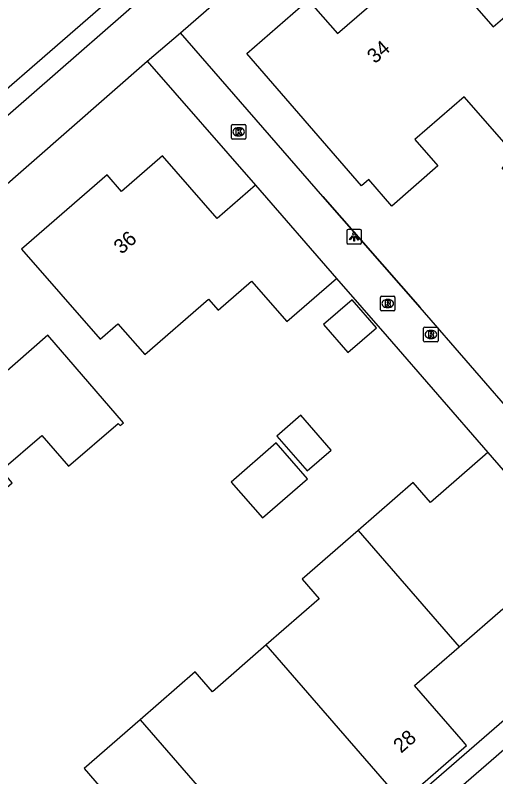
# Model space of a CAD drawing. Extents: x 155888 to 156864, y 383882 to 384671.
# Drawn here: x 156044.5 to 156077.4, y 384100.3 to 384152.6 of the extents above; entities that cross this region are included whole.
import ezdxf

# ---------------------------------------------------------------- set-up
doc = ezdxf.new("R2010")
doc.units = 0
for name, color, linetype in [('IMGEO_Kolk', 7, 'Continuous'), ('IMGEO_Lichtpunt', 7, 'Continuous'), ('IMGEO_Muur', 7, 'Continuous'), ('IMGEO_Pand', 7, 'Continuous'), ('IMGEO_Pand_nummerreeks', 7, 'Continuous'), ('IMGEO_Pand_overbouw', 7, 'Continuous'), ('IMGEO_Rijbaan_lokaal_gesloten', 7, 'Continuous'), ('IMGEO_Rioolput', 7, 'Continuous'), ('IMGEO_Voetpad_open', 7, 'Continuous')]:
    doc.layers.add(name, color=color, linetype=linetype)

msp = doc.modelspace()

# ---------------------------------------------------------------- linework, layer by layer
at = {"layer": 'IMGEO_Kolk'}
for p, q in [((156059.363, 384145.059), (156060.215, 384145.059)), ((156059.288, 384144.133), (156059.288, 384144.985)), ((156059.776, 384144.839), (156059.801, 384144.839)), ((156060.289, 384144.985), (156060.289, 384144.133)), ((156060.215, 384144.059), (156059.363, 384144.059)), ((156059.799, 384144.279), (156059.774, 384144.279))]:
    msp.add_line(p, q, dxfattribs=at)
for points in [[(156059.363, 384145.059), (156060.215, 384145.059)], [(156059.288, 384144.133), (156059.288, 384144.985)], [(156059.609, 384144.759), (156059.732, 384144.759), (156059.732, 384144.608), (156059.862, 384144.759), (156060.026, 384144.759), (156059.88, 384144.608), (156060.033, 384144.359), (156059.881, 384144.359), (156059.796, 384144.523), (156059.732, 384144.456), (156059.732, 384144.359), (156059.609, 384144.359), (156059.609, 384144.759)], [(156060.289, 384144.985), (156060.289, 384144.133)], [(156060.215, 384144.059), (156059.363, 384144.059)]]:
    msp.add_lwpolyline(points, dxfattribs=at)
for centre, start, end in [((156059.365, 384144.983), 91.552, 178.448), ((156059.365, 384144.983), 91.552, 178.448), ((156060.213, 384144.983), 1.552, 88.448), ((156060.213, 384144.983), 1.552, 88.448), ((156059.365, 384144.135), 181.552, 268.448), ((156059.365, 384144.135), 181.552, 268.448), ((156060.213, 384144.135), 271.552, 358.448), ((156060.213, 384144.135), 271.552, 358.448)]:
    msp.add_arc(centre, 0.0765, start, end, dxfattribs=at)
for centre, major_axis, ratio, start_param, end_param in [((156059.775, 384144.559), (-0.387, 0.002), 0.722429, 4.712389, 7.853982), ((156059.8, 384144.559), (-0.39, 0.002), 0.717154, 1.570796, 4.712389)]:
    msp.add_ellipse(centre, major_axis=major_axis, ratio=ratio, start_param=start_param, end_param=end_param, dxfattribs=at)
at = {"layer": 'IMGEO_Lichtpunt'}
for p, q in [((156067.218, 384137.759), (156067.218, 384136.952)), ((156067.218, 384137.759), (156067.218, 384136.952)), ((156068.12, 384137.854), (156067.312, 384137.854)), ((156068.12, 384137.854), (156067.312, 384137.854)), ((156068.214, 384136.952), (156068.214, 384137.759)), ((156068.214, 384136.952), (156068.214, 384137.759)), ((156067.312, 384136.858), (156068.12, 384136.858)), ((156067.312, 384136.858), (156068.12, 384136.858))]:
    msp.add_line(p, q, dxfattribs=at)
for points in [[(156067.592, 384137.423), (156067.631, 384137.395), (156067.443, 384137.133), (156067.405, 384137.16), (156067.592, 384137.423)], [(156067.694, 384137.375), (156067.741, 384137.375), (156067.741, 384137.053), (156067.694, 384137.053), (156067.694, 384137.375)], [(156067.804, 384137.395), (156067.842, 384137.422), (156068.029, 384137.16), (156067.99, 384137.132), (156067.804, 384137.395)]]:
    msp.add_lwpolyline(points, dxfattribs=at)
msp.add_circle((156067.717, 384137.557), 0.0994, dxfattribs=at)
for centre, start, end in [((156067.312, 384137.759), 90, 180), ((156067.312, 384137.759), 90, 180), ((156068.12, 384137.759), 0, 90), ((156068.12, 384137.759), 0, 90), ((156067.312, 384136.952), 180, 270), ((156067.312, 384136.952), 180, 270), ((156068.12, 384136.952), 270, 0), ((156068.12, 384136.952), 270, 360)]:
    msp.add_arc(centre, 0.0946, start, end, dxfattribs=at)
at = {"layer": 'IMGEO_Muur'}
for points in [[(156065.559, 384140.115), (156072.254, 384132.504)], [(156066.498, 384134.486), (156069.973, 384130.498)]]:
    msp.add_lwpolyline(points, dxfattribs=at)
at = {"layer": 'IMGEO_Pand'}
for points in [[(156080.234, 384139.361), (156077.863, 384142.085), (156078.799, 384142.9), (156075.259, 384146.968), (156071.885, 384144.032), (156073.462, 384142.221), (156070.292, 384139.462), (156068.71, 384141.281), (156068.227, 384140.861), (156060.347, 384149.929), (156064.566, 384153.595), (156066.561, 384151.3), (156070.043, 384154.326), (156072.878, 384156.789), (156077.25, 384151.765), (156078.043, 384152.455), (156083.1, 384146.644), (156085.471, 384143.92), (156081.936, 384140.842)], [(156060.939, 384140.901), (156058.302, 384138.603), (156054.555, 384142.902), (156051.76, 384140.467), (156050.764, 384141.61), (156044.892, 384136.493), (156050.276, 384130.315), (156051.502, 384131.383), (156053.349, 384129.264), (156057.718, 384133.071), (156058.375, 384132.317), (156060.665, 384134.313), (156063.089, 384131.532), (156066.498, 384134.486)], [(156060.939, 384140.901), (156066.498, 384134.486)], [(156067.285, 384129.413), (156069.236, 384131.104), (156067.567, 384133.029), (156065.616, 384131.339), (156067.285, 384129.413)], [(156040.149, 384116.917), (156044.251, 384120.459), (156043.505, 384121.324), (156046.28, 384123.72), (156048.113, 384121.597), (156051.525, 384124.544), (156051.656, 384124.392), (156051.884, 384124.589), (156046.703, 384130.589), (156043.311, 384127.654), (156039.612, 384131.91), (156037.93, 384130.448), (156037.204, 384131.284), (156034.303, 384128.763), (156035.041, 384127.914), (156033.379, 384126.47), (156037.473, 384121.726), (156036.639, 384120.981), (156040.149, 384116.917)], [(156064.496, 384121.274), (156066.14, 384122.702), (156064.054, 384125.103), (156062.41, 384123.675), (156064.496, 384121.274)], [(156064.509, 384120.736), (156062.367, 384123.202), (156059.274, 384120.515), (156061.416, 384118.049), (156064.509, 384120.736)], [(156076.889, 384122.539), (156072.948, 384119.116), (156071.768, 384120.475), (156067.993, 384117.196)], [(156076.889, 384122.539), (156086.213, 384111.78)], [(156067.993, 384117.196), (156064.143, 384113.853), (156065.323, 384112.494), (156061.68, 384109.33)], [(156067.993, 384117.196), (156074.91, 384109.195)], [(156074.91, 384109.195), (156077.908, 384111.802), (156081.257, 384107.931), (156081.474, 384107.68), (156086.213, 384111.78)], [(156061.68, 384109.33), (156057.985, 384106.121), (156056.805, 384107.48), (156053.02, 384104.194)], [(156071.003, 384098.579), (156061.68, 384109.33)], [(156071.003, 384098.579), (156075.429, 384102.423), (156075.212, 384102.673), (156071.855, 384106.538), (156074.91, 384109.195)], [(156053.02, 384104.194), (156049.179, 384100.858), (156050.36, 384099.499), (156046.712, 384096.331)], [(156053.02, 384104.194), (156059.957, 384096.196)]]:
    msp.add_lwpolyline(points, dxfattribs=at)
at = {"layer": 'IMGEO_Pand_overbouw'}
msp.add_lwpolyline([(156067.638, 384156.278), (156064.566, 384153.595), (156066.561, 384151.3), (156070.043, 384154.326), (156068.259, 384156.379), (156067.848, 384156.031)], close=True, dxfattribs=at)
at = {"layer": 'IMGEO_Rijbaan_lokaal_gesloten'}
msp.add_lwpolyline([(155960.096, 384074.77), (155985.962, 384097.201), (156000, 384109.463), (156037.058, 384141.597), (156052.579, 384155.078), (156079.587, 384178.584), (156099.166, 384195.602), (156142.141, 384232.995)], dxfattribs=at)
at = {"layer": 'IMGEO_Rioolput'}
for p, q in [((156069.514, 384132.344), (156069.514, 384133.196)), ((156069.589, 384133.27), (156070.441, 384133.27)), ((156070.002, 384133.05), (156070.027, 384133.05)), ((156070.515, 384133.196), (156070.515, 384132.344)), ((156070.025, 384132.49), (156070, 384132.49)), ((156070.441, 384132.27), (156069.589, 384132.27)), ((156072.482, 384130.221), (156072.482, 384131.073)), ((156072.557, 384131.147), (156073.409, 384131.147)), ((156072.97, 384130.927), (156072.995, 384130.927)), ((156073.483, 384131.073), (156073.483, 384130.221)), ((156072.993, 384130.367), (156072.968, 384130.367)), ((156073.409, 384130.147), (156072.557, 384130.147))]:
    msp.add_line(p, q, dxfattribs=at)
for points in [[(156069.514, 384132.344), (156069.514, 384133.196)], [(156069.589, 384133.27), (156070.441, 384133.27)], [(156070.103, 384132.968), (156069.851, 384132.97), (156069.851, 384132.57)], [(156070.515, 384133.196), (156070.515, 384132.344)], [(156069.851, 384132.57), (156069.975, 384132.57), (156069.975, 384132.732), (156069.986, 384132.732)], [(156070.029, 384132.889), (156069.975, 384132.889), (156069.975, 384132.808)], [(156069.975, 384132.808), (156070.027, 384132.808)], [(156070.033, 384132.703), (156070.104, 384132.57), (156070.244, 384132.57), (156070.179, 384132.696)], [(156070.441, 384132.27), (156069.589, 384132.27)], [(156072.482, 384130.221), (156072.482, 384131.073)], [(156072.557, 384131.147), (156073.409, 384131.147)], [(156073.483, 384131.073), (156073.483, 384130.221)], [(156073.071, 384130.845), (156072.819, 384130.847), (156072.819, 384130.447)], [(156072.819, 384130.447), (156072.943, 384130.447), (156072.943, 384130.609), (156072.954, 384130.609)], [(156072.997, 384130.766), (156072.943, 384130.766), (156072.943, 384130.685)], [(156072.943, 384130.685), (156072.995, 384130.685)], [(156073.001, 384130.58), (156073.072, 384130.447), (156073.212, 384130.447), (156073.147, 384130.573)], [(156073.409, 384130.147), (156072.557, 384130.147)]]:
    msp.add_lwpolyline(points, dxfattribs=at)
for centre, radius, start, end in [((156069.591, 384133.194), 0.0765, 91.552, 178.448), ((156069.591, 384133.194), 0.0765, 91.552, 178.448), ((156070.102, 384132.858), 0.109, 350.3612, 89.416), ((156070.439, 384133.194), 0.0765, 1.552, 88.448), ((156070.439, 384133.194), 0.0765, 1.552, 88.448), ((156069.985, 384132.679), 0.0533, 26.0293, 88.6989), ((156070.011, 384132.997), 0.19, 274.7715, 282.9687), ((156070.035, 384132.793), 0.0964, 77.0061, 93.1865), ((156070.049, 384132.85), 0.0378, 276.6634, 79.6772), ((156070.1, 384132.858), 0.112, 277.5842, 350.9817), ((156070.084, 384132.643), 0.108, 29.5134, 73.7905), ((156069.591, 384132.346), 0.0765, 181.552, 268.448), ((156069.591, 384132.346), 0.0765, 181.552, 268.448), ((156070.439, 384132.346), 0.0765, 271.552, 358.448), ((156070.439, 384132.346), 0.0765, 271.552, 358.448), ((156072.559, 384131.071), 0.0765, 91.552, 178.448), ((156072.559, 384131.071), 0.0765, 91.552, 178.448), ((156073.407, 384131.071), 0.0765, 1.552, 88.448), ((156073.407, 384131.071), 0.0765, 1.552, 88.448), ((156072.953, 384130.556), 0.0533, 26.0293, 88.6989), ((156072.979, 384130.874), 0.19, 274.7715, 282.9687), ((156073.003, 384130.67), 0.0964, 77.0061, 93.1865), ((156073.017, 384130.727), 0.0378, 276.6634, 79.6772), ((156073.07, 384130.735), 0.109, 350.3612, 89.416), ((156073.068, 384130.735), 0.112, 277.5842, 350.9817), ((156073.052, 384130.52), 0.108, 29.5134, 73.7905), ((156072.559, 384130.223), 0.0765, 181.552, 268.448), ((156072.559, 384130.223), 0.0765, 181.552, 268.448), ((156073.407, 384130.223), 0.0765, 271.552, 358.448), ((156073.407, 384130.223), 0.0765, 271.552, 358.448)]:
    msp.add_arc(centre, radius, start, end, dxfattribs=at)
for centre, major_axis, ratio, start_param, end_param in [((156070.001, 384132.77), (-0.387, 0.002), 0.722429, 4.712389, 7.853982), ((156070.026, 384132.77), (-0.39, 0.002), 0.717154, 1.570796, 4.712389), ((156072.969, 384130.647), (-0.387, 0.002), 0.722429, 4.712389, 7.853982), ((156072.994, 384130.647), (-0.39, 0.002), 0.717154, 1.570796, 4.712389)]:
    msp.add_ellipse(centre, major_axis=major_axis, ratio=ratio, start_param=start_param, end_param=end_param, dxfattribs=at)
at = {"layer": 'IMGEO_Voetpad_open'}
for points in [[(156142.785, 384233.533), (156143.773, 384232.361), (156081.118, 384178.034), (156053.511, 384154.06), (156037.984, 384140.492), (156002.735, 384109.772), (156000, 384107.534), (155986.803, 384096.014), (155961.077, 384073.632)], [(156055.794, 384151.364), (156083.269, 384175.304), (156146.041, 384229.773)], [(156053.505, 384149.41), (156055.794, 384151.364)], [(156079.139, 384124.535), (156072.254, 384132.504), (156065.559, 384140.115), (156055.794, 384151.364)], [(155963.356, 384071.023), (155988.995, 384093.32), (156000, 384102.992), (156014.631, 384115.561), (156040.198, 384137.755), (156053.505, 384149.41)], [(156053.505, 384149.41), (156060.939, 384140.901)], [(156066.498, 384134.486), (156069.973, 384130.498), (156076.889, 384122.539)], [(156086.442, 384111.494), (156000, 384036.51), (155996.263, 384033.139)], [(156070.574, 384095.715), (156087.459, 384110.362)]]:
    msp.add_lwpolyline(points, dxfattribs=at)

# ---------------------------------------------------------------- texts
at = {"layer": 'IMGEO_Pand_nummerreeks'}
for s, rotation, p in [('34', 40.9894, (156069.137, 384149.194)), ('36', 41.0623, (156051.753, 384136.11)), ('28', 40.9738, (156070.934, 384101.858))]:
    msp.add_text(s, height=1, rotation=rotation, dxfattribs=at).set_placement(p)

doc.saveas('drawing.dxf')
